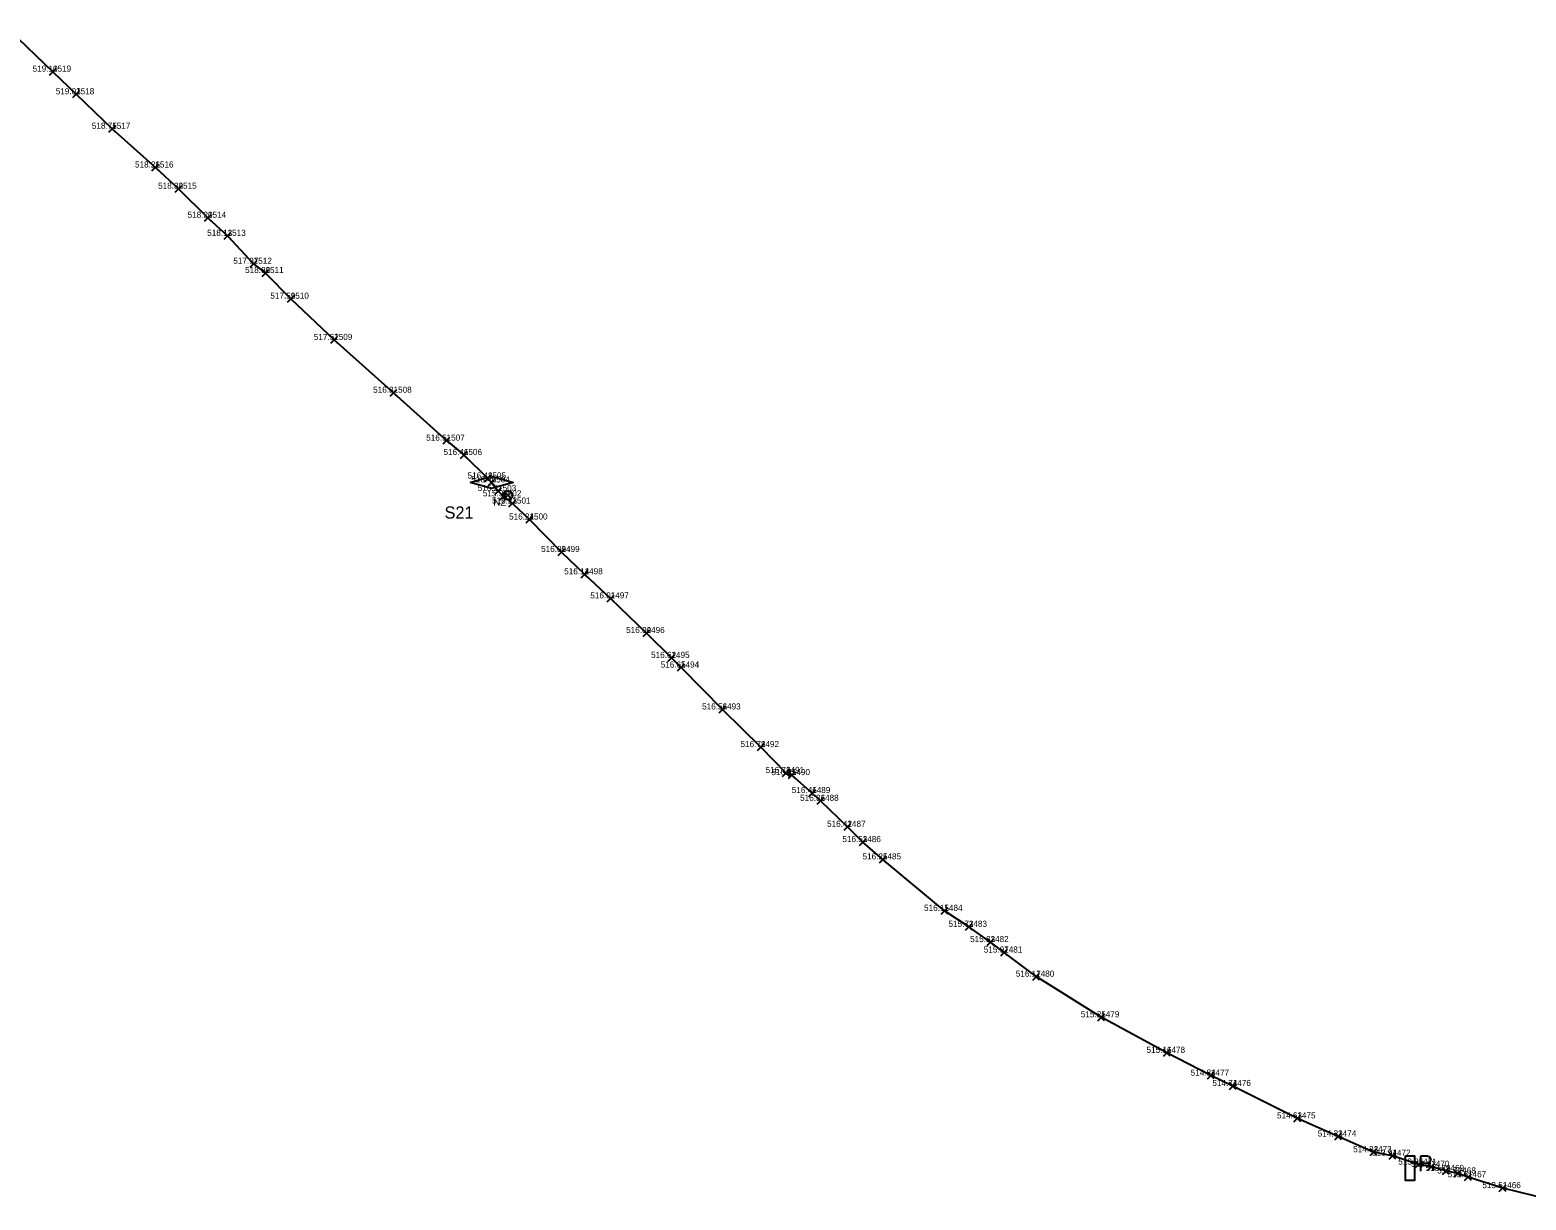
# Model space of a CAD drawing. Extents: x -874041 to -866452, y -1055592 to -1049889.
# Drawn here: x -872799.1 to -872554.3, y -1055581.9 to -1055390.5 of the extents above; entities that cross this region are included whole.
import ezdxf

# ---------------------------------------------------------------- set-up
doc = ezdxf.new("R2010")
doc.units = 0
for name, color, linetype in [('Vrstva 32', 7, 'Continuous'), ('Vrstva 33', 7, 'Continuous'), ('Vrstva 60', 7, 'Continuous'), ('Vrstva 61', 7, 'Continuous'), ('Vrstva 63', 7, 'Continuous')]:
    doc.layers.add(name, color=color, linetype=linetype)

msp = doc.modelspace()

# ---------------------------------------------------------------- linework, layer by layer
at = {"layer": 'Vrstva 32'}
for points in [[(-872802.49, -1055390.49), (-872795.31, -1055397.32), (-872791.53, -1055401.02), (-872785.62, -1055406.67), (-872778.56, -1055413), (-872774.78, -1055416.47), (-872769.96, -1055421.23), (-872766.75, -1055424.18), (-872762.48, -1055428.75), (-872760.55, -1055430.26), (-872756.42, -1055434.47), (-872749.31, -1055441.21), (-872739.6, -1055449.85), (-872730.92, -1055457.68), (-872728.1, -1055460.03), (-872724.16, -1055463.88), (-872723.55, -1055464.52), (-872722.5, -1055465.92), (-872721.66, -1055466.79), (-872720.16, -1055467.98), (-872717.37, -1055470.59), (-872712.13, -1055475.9), (-872708.35, -1055479.55), (-872704.08, -1055483.49), (-872698.22, -1055489.16), (-872694.14, -1055493.23), (-872692.57, -1055494.81), (-872685.79, -1055501.66), (-872679.51, -1055507.82), (-872675.4, -1055512.05), (-872674.45, -1055512.4), (-872671.12, -1055515.34), (-872669.76, -1055516.61), (-872665.35, -1055520.86), (-872662.85, -1055523.36)], [(-872727.05, -1055464.52), (-872723.55, -1055463.52), (-872720.05, -1055464.52), (-872723.55, -1055465.52), (-872727.05, -1055464.52)], [(-872550.14, -1055581.92), (-872558.16, -1055579.97), (-872563.83, -1055578.18), (-872565.52, -1055577.57), (-872567.45, -1055577.16), (-872569.85, -1055576.47), (-872571.91, -1055576.12), (-872576.2, -1055574.67), (-872579.29, -1055574.09), (-872585.09, -1055571.52), (-872591.75, -1055568.56), (-872602.32, -1055563.26), (-872605.88, -1055561.56), (-872613.09, -1055557.84), (-872623.84, -1055552.02), (-872634.48, -1055545.37), (-872639.71, -1055541.43), (-872641.95, -1055539.72), (-872645.49, -1055537.22), (-872649.49, -1055534.61), (-872659.55, -1055526.19), (-872662.85, -1055523.36)]]:
    msp.add_lwpolyline(points, dxfattribs=at)
at = {"layer": 'Vrstva 33'}
msp.add_lwpolyline([(-872574.08, -1055574.69), (-872572.59, -1055574.69), (-872572.59, -1055578.72), (-872574.08, -1055578.72)], close=True, dxfattribs=at)
for points in [[(-872571.54, -1055577.19), (-872571.54, -1055574.68)], [(-872571.54, -1055574.68), (-872570.5, -1055574.68)], [(-872570.5, -1055574.68), (-872570.19, -1055574.78), (-872569.96, -1055575.19), (-872569.96, -1055575.41), (-872570.19, -1055575.83), (-872570.5, -1055575.92)], [(-872570.5, -1055575.92), (-872571.54, -1055575.92)]]:
    msp.add_lwpolyline(points, dxfattribs=at)
at = {"layer": 'Vrstva 60'}
for p, q in [((-872795.86, -1055397.87), (-872794.76, -1055396.77)), ((-872794.76, -1055397.87), (-872795.86, -1055396.77)), ((-872792.08, -1055401.57), (-872790.98, -1055400.47)), ((-872790.98, -1055401.57), (-872792.08, -1055400.47)), ((-872786.17, -1055407.22), (-872785.07, -1055406.12)), ((-872785.07, -1055407.22), (-872786.17, -1055406.12)), ((-872779.11, -1055413.55), (-872778.01, -1055412.45)), ((-872778.01, -1055413.55), (-872779.11, -1055412.45)), ((-872775.33, -1055417.02), (-872774.23, -1055415.92)), ((-872774.23, -1055417.02), (-872775.33, -1055415.92)), ((-872770.51, -1055421.78), (-872769.41, -1055420.68)), ((-872769.41, -1055421.78), (-872770.51, -1055420.68)), ((-872767.3, -1055424.73), (-872766.2, -1055423.63)), ((-872766.2, -1055424.73), (-872767.3, -1055423.63)), ((-872763.03, -1055429.3), (-872761.93, -1055428.2)), ((-872761.93, -1055429.3), (-872763.03, -1055428.2)), ((-872761.1, -1055430.81), (-872760, -1055429.71)), ((-872760, -1055430.81), (-872761.1, -1055429.71)), ((-872756.97, -1055435.02), (-872755.87, -1055433.92)), ((-872755.87, -1055435.02), (-872756.97, -1055433.92)), ((-872749.86, -1055441.76), (-872748.76, -1055440.66)), ((-872748.76, -1055441.76), (-872749.86, -1055440.66)), ((-872740.15, -1055450.4), (-872739.05, -1055449.3)), ((-872739.05, -1055450.4), (-872740.15, -1055449.3)), ((-872731.47, -1055458.23), (-872730.37, -1055457.13)), ((-872730.37, -1055458.23), (-872731.47, -1055457.13)), ((-872728.65, -1055460.58), (-872727.55, -1055459.48)), ((-872727.55, -1055460.58), (-872728.65, -1055459.48)), ((-872724.71, -1055464.43), (-872723.61, -1055463.33)), ((-872723.61, -1055464.43), (-872724.71, -1055463.33)), ((-872724.1, -1055465.07), (-872723, -1055463.97)), ((-872723, -1055465.07), (-872724.1, -1055463.97)), ((-872723.05, -1055466.47), (-872721.95, -1055465.37)), ((-872721.95, -1055466.47), (-872723.05, -1055465.37)), ((-872722.21, -1055467.34), (-872721.11, -1055466.24)), ((-872721.11, -1055467.34), (-872722.21, -1055466.24)), ((-872720.71, -1055468.53), (-872719.61, -1055467.43)), ((-872719.61, -1055468.53), (-872720.71, -1055467.43)), ((-872717.92, -1055471.14), (-872716.82, -1055470.04)), ((-872716.82, -1055471.14), (-872717.92, -1055470.04)), ((-872712.68, -1055476.45), (-872711.58, -1055475.35)), ((-872711.58, -1055476.45), (-872712.68, -1055475.35)), ((-872708.9, -1055480.1), (-872707.8, -1055479)), ((-872707.8, -1055480.1), (-872708.9, -1055479)), ((-872704.63, -1055484.04), (-872703.53, -1055482.94)), ((-872703.53, -1055484.04), (-872704.63, -1055482.94)), ((-872698.77, -1055489.71), (-872697.67, -1055488.61)), ((-872697.67, -1055489.71), (-872698.77, -1055488.61)), ((-872694.69, -1055493.78), (-872693.59, -1055492.68)), ((-872693.59, -1055493.78), (-872694.69, -1055492.68)), ((-872693.12, -1055495.36), (-872692.02, -1055494.26)), ((-872692.02, -1055495.36), (-872693.12, -1055494.26)), ((-872686.34, -1055502.21), (-872685.24, -1055501.11)), ((-872685.24, -1055502.21), (-872686.34, -1055501.11)), ((-872680.06, -1055508.37), (-872678.96, -1055507.27)), ((-872678.96, -1055508.37), (-872680.06, -1055507.27)), ((-872675.95, -1055512.6), (-872674.85, -1055511.5)), ((-872674.85, -1055512.6), (-872675.95, -1055511.5)), ((-872675, -1055512.95), (-872673.9, -1055511.85)), ((-872673.9, -1055512.95), (-872675, -1055511.85)), ((-872671.67, -1055515.89), (-872670.57, -1055514.79)), ((-872670.57, -1055515.89), (-872671.67, -1055514.79)), ((-872670.31, -1055517.16), (-872669.21, -1055516.06)), ((-872669.21, -1055517.16), (-872670.31, -1055516.06)), ((-872665.9, -1055521.41), (-872664.8, -1055520.31)), ((-872664.8, -1055521.41), (-872665.9, -1055520.31)), ((-872663.4, -1055523.91), (-872662.3, -1055522.81)), ((-872662.3, -1055523.91), (-872663.4, -1055522.81)), ((-872660.1, -1055526.74), (-872659, -1055525.64)), ((-872659, -1055526.74), (-872660.1, -1055525.64)), ((-872650.04, -1055535.16), (-872648.94, -1055534.06)), ((-872648.94, -1055535.16), (-872650.04, -1055534.06)), ((-872646.04, -1055537.77), (-872644.94, -1055536.67)), ((-872644.94, -1055537.77), (-872646.04, -1055536.67)), ((-872642.5, -1055540.27), (-872641.4, -1055539.17)), ((-872641.4, -1055540.27), (-872642.5, -1055539.17)), ((-872640.26, -1055541.98), (-872639.16, -1055540.88)), ((-872639.16, -1055541.98), (-872640.26, -1055540.88)), ((-872635.03, -1055545.92), (-872633.93, -1055544.82)), ((-872633.93, -1055545.92), (-872635.03, -1055544.82)), ((-872624.39, -1055552.57), (-872623.29, -1055551.47)), ((-872623.29, -1055552.57), (-872624.39, -1055551.47)), ((-872613.64, -1055558.39), (-872612.54, -1055557.29)), ((-872612.54, -1055558.39), (-872613.64, -1055557.29)), ((-872606.43, -1055562.11), (-872605.33, -1055561.01)), ((-872605.33, -1055562.11), (-872606.43, -1055561.01)), ((-872602.87, -1055563.81), (-872601.77, -1055562.71)), ((-872601.77, -1055563.81), (-872602.87, -1055562.71)), ((-872592.3, -1055569.11), (-872591.2, -1055568.01)), ((-872591.2, -1055569.11), (-872592.3, -1055568.01)), ((-872585.64, -1055572.07), (-872584.54, -1055570.97)), ((-872584.54, -1055572.07), (-872585.64, -1055570.97)), ((-872579.84, -1055574.64), (-872578.74, -1055573.54)), ((-872578.74, -1055574.64), (-872579.84, -1055573.54)), ((-872576.75, -1055575.22), (-872575.65, -1055574.12)), ((-872575.65, -1055575.22), (-872576.75, -1055574.12)), ((-872572.46, -1055576.67), (-872571.36, -1055575.57)), ((-872571.36, -1055576.67), (-872572.46, -1055575.57)), ((-872570.4, -1055577.02), (-872569.3, -1055575.92)), ((-872569.3, -1055577.02), (-872570.4, -1055575.92)), ((-872568, -1055577.71), (-872566.9, -1055576.61)), ((-872566.9, -1055577.71), (-872568, -1055576.61)), ((-872566.07, -1055578.12), (-872564.97, -1055577.02)), ((-872564.97, -1055578.12), (-872566.07, -1055577.02)), ((-872564.38, -1055578.73), (-872563.28, -1055577.63)), ((-872563.28, -1055578.73), (-872564.38, -1055577.63)), ((-872558.71, -1055580.52), (-872557.61, -1055579.42)), ((-872557.61, -1055580.52), (-872558.71, -1055579.42))]:
    msp.add_line(p, q, dxfattribs=at)
at = {"layer": 'Vrstva 63'}
for p, q in [((-872721.42, -1055467.14), (-872720.36, -1055466.09)), ((-872721.42, -1055466.1), (-872720.36, -1055467.14))]:
    msp.add_line(p, q, dxfattribs=at)
msp.add_circle((-872720.89, -1055466.62), 0.748, dxfattribs=at)

# ---------------------------------------------------------------- texts
at = {"layer": 'Vrstva 32'}
msp.add_text('S21', height=2, dxfattribs=at).set_placement((-872731.26, -1055470.44))
at = {"layer": 'Vrstva 60'}
for s, p in [('1519', (-872795.31, -1055397.32)), ('1518', (-872791.53, -1055401.02)), ('1517', (-872785.62, -1055406.67)), ('1516', (-872778.56, -1055413)), ('1515', (-872774.78, -1055416.47)), ('1514', (-872769.96, -1055421.23)), ('1513', (-872766.75, -1055424.18)), ('1512', (-872762.48, -1055428.75)), ('1511', (-872760.55, -1055430.26)), ('1510', (-872756.42, -1055434.47)), ('1509', (-872749.31, -1055441.21)), ('1508', (-872739.6, -1055449.85)), ('1507', (-872730.92, -1055457.68)), ('1506', (-872728.1, -1055460.03)), ('1505', (-872724.16, -1055463.88)), ('1504', (-872723.55, -1055464.52)), ('1503', (-872722.5, -1055465.92)), ('1502', (-872721.66, -1055466.79)), ('1501', (-872720.16, -1055467.98)), ('1500', (-872717.37, -1055470.59)), ('1499', (-872712.13, -1055475.9)), ('1498', (-872708.35, -1055479.55)), ('1497', (-872704.08, -1055483.49)), ('1496', (-872698.22, -1055489.16)), ('1495', (-872694.14, -1055493.23)), ('1494', (-872692.57, -1055494.81)), ('1493', (-872685.79, -1055501.66)), ('1492', (-872679.51, -1055507.82)), ('1491', (-872675.4, -1055512.05)), ('1490', (-872674.45, -1055512.4)), ('1489', (-872671.12, -1055515.34)), ('1488', (-872669.76, -1055516.61)), ('1487', (-872665.35, -1055520.86)), ('1486', (-872662.85, -1055523.36)), ('1485', (-872659.55, -1055526.19)), ('1484', (-872649.49, -1055534.61)), ('1483', (-872645.49, -1055537.22)), ('1482', (-872641.95, -1055539.72)), ('1481', (-872639.71, -1055541.43)), ('1480', (-872634.48, -1055545.37)), ('1479', (-872623.84, -1055552.02)), ('1478', (-872613.09, -1055557.84)), ('1477', (-872605.88, -1055561.56)), ('1476', (-872602.32, -1055563.26)), ('1475', (-872591.75, -1055568.56)), ('1474', (-872585.09, -1055571.52)), ('1473', (-872579.29, -1055574.09)), ('1472', (-872576.2, -1055574.67)), ('1471', (-872571.91, -1055576.12)), ('1470', (-872569.85, -1055576.47)), ('1469', (-872567.45, -1055577.16)), ('1468', (-872565.52, -1055577.57)), ('1467', (-872563.83, -1055578.18)), ('1466', (-872558.16, -1055579.97))]:
    msp.add_text(s, height=1, dxfattribs=at).set_placement(p)
at = {"layer": 'Vrstva 61'}
for s, p in [('519.10 ', (-872798.64, -1055397.32)), ('519.03 ', (-872794.86, -1055401.02)), ('518.75 ', (-872788.95, -1055406.67)), ('518.26 ', (-872781.89, -1055413)), ('518.30 ', (-872778.11, -1055416.47)), ('518.20 ', (-872773.29, -1055421.23)), ('518.13 ', (-872770.08, -1055424.18)), ('517.97 ', (-872765.81, -1055428.75)), ('518.00 ', (-872763.88, -1055430.26)), ('517.59 ', (-872759.75, -1055434.47)), ('517.52 ', (-872752.64, -1055441.21)), ('516.81 ', (-872742.93, -1055449.85)), ('516.51 ', (-872734.25, -1055457.68)), ('516.46 ', (-872731.43, -1055460.03)), ('516.48 ', (-872727.49, -1055463.88)), ('516.40 ', (-872726.88, -1055464.52)), ('516.21 ', (-872725.83, -1055465.92)), ('515.90 ', (-872724.99, -1055466.79)), ('516.23 ', (-872723.49, -1055467.98)), ('516.24 ', (-872720.7, -1055470.59)), ('516.09 ', (-872715.46, -1055475.9)), ('516.14 ', (-872711.68, -1055479.55)), ('516.01 ', (-872707.41, -1055483.49)), ('516.00 ', (-872701.55, -1055489.16)), ('516.62 ', (-872697.47, -1055493.23)), ('516.65 ', (-872695.9, -1055494.81)), ('516.56 ', (-872689.12, -1055501.66)), ('516.78 ', (-872682.84, -1055507.82)), ('516.78 ', (-872678.73, -1055512.05)), ('516.45 ', (-872677.78, -1055512.4)), ('516.46 ', (-872674.45, -1055515.34)), ('516.36 ', (-872673.09, -1055516.61)), ('516.42 ', (-872668.68, -1055520.86)), ('516.53 ', (-872666.18, -1055523.36)), ('516.25 ', (-872662.88, -1055526.19)), ('516.15 ', (-872652.82, -1055534.61)), ('515.73 ', (-872648.82, -1055537.22)), ('515.83 ', (-872645.28, -1055539.72)), ('515.97 ', (-872643.04, -1055541.43)), ('516.17 ', (-872637.81, -1055545.37)), ('515.25 ', (-872627.17, -1055552.02)), ('515.16 ', (-872616.42, -1055557.84)), ('514.84 ', (-872609.21, -1055561.56)), ('514.74 ', (-872605.65, -1055563.26)), ('514.63 ', (-872595.08, -1055568.56)), ('514.33 ', (-872588.42, -1055571.52)), ('514.33 ', (-872582.62, -1055574.09)), ('513.94 ', (-872579.53, -1055574.67)), ('513.95 ', (-872575.24, -1055576.12)), ('513.92 ', (-872573.18, -1055576.47)), ('513.79 ', (-872570.78, -1055577.16)), ('513.72 ', (-872568.85, -1055577.57)), ('513.61 ', (-872567.16, -1055578.18)), ('513.51 ', (-872561.49, -1055579.97))]:
    msp.add_text(s, height=1, dxfattribs=at).set_placement(p)
at = {"layer": 'Vrstva 63'}
msp.add_text('NZ', height=1.2, dxfattribs=at).set_placement((-872723.28, -1055468.32))

doc.saveas('drawing.dxf')
